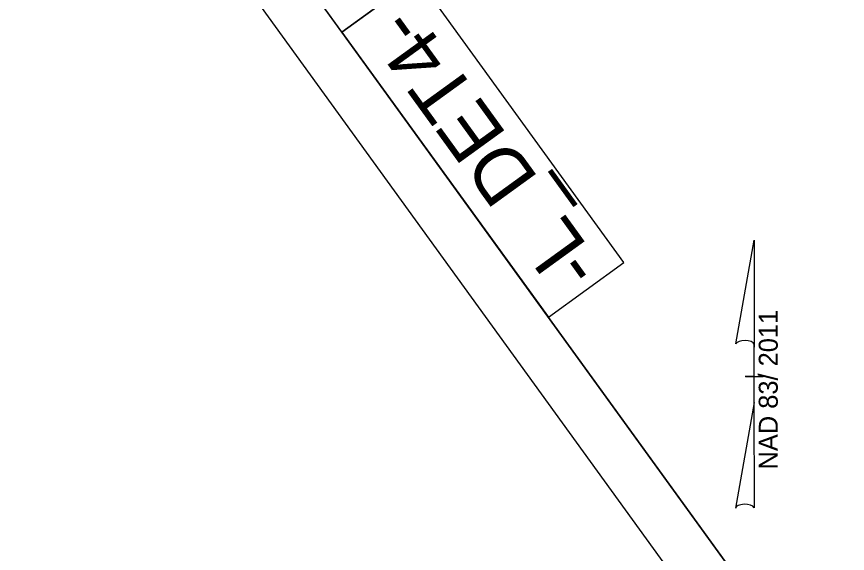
# Model space of a CAD drawing. Extents: x 474248 to 476123, y 501895 to 503900.
# Drawn here: x 474248.4 to 474619.9, y 502862.5 to 503102.6 of the extents above; entities that cross this region are included whole.
import ezdxf

# ---------------------------------------------------------------- set-up
doc = ezdxf.new("R2010")
doc.units = 0
for name, color, linetype in [('Old_Level_1', 7, 'Continuous'), ('Prop Grid Mask', 7, 'Continuous'), ('Prop North Arrow NAD83 for Plan Sheets CELL', 7, 'Continuous'), ('Scratch_Level_5', 7, 'Continuous'), ('Sheet Layout Plan Border', 7, 'Continuous'), ('Sheet Plan CELL', 7, 'Continuous'), ('Sheet Plot Border Outside CELL', 7, 'Continuous')]:
    doc.layers.add(name, color=color, linetype=linetype)

msp = doc.modelspace()

# ---------------------------------------------------------------- linework, layer by layer
at = {"layer": 'Prop Grid Mask'}
msp.add_lwpolyline([(474393.92, 503095.62), (474486.21, 502968.16), (474519.99, 502992.62), (474427.7, 503120.08)], close=True, dxfattribs=at)
at = {"layer": 'Prop North Arrow NAD83 for Plan Sheets CELL'}
for p, q in [((474570.04, 502956.19), (474578.24, 503002.54)), ((474578.29, 503002.54), (474578.24, 503002.54)), ((474578.29, 503002.54), (474578.24, 503002.54)), ((474578.29, 503002.54), (474578.29, 502954.74)), ((474578.29, 502929.94), (474578.29, 502956.14)), ((474578.29, 502954.74), (474578.29, 502956.09)), ((474574.29, 502941.54), (474574.24, 502941.54)), ((474577.84, 502941.54), (474574.29, 502941.54)), ((474574.34, 502941.54), (474582.34, 502941.54)), ((474578.29, 502929.94), (474569.94, 502882.69)), ((474578.34, 502882.89), (474578.29, 502929.94))]:
    msp.add_line(p, q, dxfattribs=at)
for centre, start_param, end_param in [((474574.17, 502955.69), 0.216388, 2.908219), ((474574.17, 502882.52), 0.201328, 3.141593)]:
    msp.add_ellipse(centre, major_axis=(4.23, -0.03), ratio=0.461098, start_param=start_param, end_param=end_param, dxfattribs=at)
at = {"layer": 'Scratch_Level_5'}
msp.add_lwpolyline([(474627.91, 502772.46), (474393.92, 503095.62), (474534.48, 503197.42), (474417.16, 503359.44), (475062.24, 503826.52), (475162.27, 503688.38), (475227.09, 503735.31), (475493.16, 503367.85)], close=True, dxfattribs=at)
at = {"layer": 'Sheet Layout Plan Border'}
msp.add_lwpolyline([(475148.79, 502314.89), (475799.67, 502786.07), (475874.95, 502840.56), (475397.53, 503499.92), (475353.89, 503468.32), (475265.23, 503590.78), (475283.66, 503604.12), (475199.91, 503719.79), (475161.57, 503692.03), (475161.57, 503692.03), (475161.57, 503692.03), (475161.57, 503692.03), (475161.57, 503692.03), (475063.52, 503827.46), (474417.16, 503359.44), (474534.48, 503197.42), (474393.91, 503095.62), (475024.42, 502224.85)], close=True, dxfattribs=at)
at = {"layer": 'Sheet Plan CELL'}
for points in [[(474276.58, 503257.68), (475156.32, 502042.7), (476006.78, 502658.5), (475127.06, 503873.46)], [(476006.78, 502658.5), (475156.35, 502042.69), (474393.91, 503095.62), (474515.45, 503183.63), (474398.14, 503345.66), (475127.06, 503873.46)], [(474393.91, 503095.62), (474276.58, 503257.68), (474296.89, 503272.34), (474414.23, 503110.33)]]:
    msp.add_lwpolyline(points, close=True, dxfattribs=at)
at = {"layer": 'Sheet Plot Border Outside CELL'}
msp.add_lwpolyline([(475235.74, 501894.66), (474248.41, 503258.24), (475135.32, 503900.43), (476122.66, 502536.85)], close=True, dxfattribs=at)

# ---------------------------------------------------------------- texts
at = {"layer": 'Old_Level_1'}
msp.add_text('-L_DET4-', height=25, rotation=125.9074, dxfattribs=at).set_placement((474510.58, 502990.82))
at = {"layer": 'Prop North Arrow NAD83 for Plan Sheets CELL'}
msp.add_text('NAD 83/ 2011', height=8.5, rotation=90, dxfattribs=at).set_placement((474588.81, 502900.02))

doc.saveas('drawing.dxf')
